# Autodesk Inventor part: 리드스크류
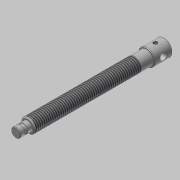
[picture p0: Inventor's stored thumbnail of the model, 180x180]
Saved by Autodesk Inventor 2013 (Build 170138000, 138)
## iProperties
Created: 2019-04
Part Number: 리드스크류
Material: 강철, 연강
Document SubType Name: Modeling
Designer: mduedu
Density: 1 g/cm^3
Author: mduedu
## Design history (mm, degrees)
sketch "스케치1"
  geometry: C1 r 6 at (0, 0); 1 further point
  constraints: 1 centre point, 1 coincident
  dimensions: "d0" = 12 diameter of C1
extrude "돌출1" new body sketch "스케치1" distance "d1" = 100; taper "d2" = 0 deg
sketch "스케치2"
  geometry: C1 r 4 at (0, 0); 1 further point
  constraints: 1 centre point, 1 coincident
  dimensions: "d3" = 8 diameter of C1
extrude "돌출2" join sketch "스케치2" distance "d4" = 10; taper "d5" = 0 deg
sketch "스케치3"
  geometry: C1 r 7 at (0, 0); 1 further point
  constraints: 1 centre point, 1 coincident
  dimensions: "d9" = 14 diameter of C1
extrude "돌출3" join sketch "스케치3" distance "d10" = 15; taper "d11" = 0 deg
feature "스레드1" dims "d12" = 90, "d13" = 0
chamfer "모따기2" distance "d14" = 1; stored, may be unused: second distance "d15" = 2, angle "d16" = 45 deg
chamfer "모따기3" distance "d17" = 0.5; stored, may be unused: second distance "d18" = 2, angle "d19" = 45 deg
chamfer "모따기4" distance "d20" = 0.5; stored, may be unused: second distance "d21" = 2, angle "d22" = 45 deg
sketch "스케치4"
  geometry: L1 (-100, -5)-(-100, 5) reference; L2 (-109.5, 4)-(-109.5, -4) reference; L3 (-109.5, 0)-(-100, 0); C1 r 1.25 at (-105, 4); 1 further point
  constraints: 2 end point, 2 midpoint, 1 centre point
  dimensions: "d23" = 2.5 diameter of C1; "d24" = 5 distance from line of C1.centre L1; "d25" = 4 distance from line of C1.centre L3
revolve "회전1" sketch "스케치4" stored, may be unused: angle "d26" = 90 deg
sketch "스케치5"
  geometry: L1 (0, -6.5)-(0, 6.5) reference; C1 r 3 at (7.5, 0); 2 further points
  constraints: 1 centre point, 1 horizontal alignment, 1 midpoint
  dimensions: "d27" = 6 diameter of C1; "d28" = 7.5 distance from line of C1.centre L1
extrude "돌출4" cut sketch "스케치5" stored distance "d29" = 15; taper "d30" = 0 deg
node "작업 평면1"
sketch "스케치6"
  geometry: L1 (0, 6.5)-(0, -6.5) reference; 2 further points
  constraints: 1 horizontal alignment
  dimensions: "d31" = 7.5 distance from line of point (-7.5, 0) L1
hole "구멍1" sketch "스케치6" at (-7.5, 0) diameter "d32" = 3.242; stored, may be unused: countersink angle "d36" = 90 deg, drill point angle "d38" = 118 deg; dims "d33" = 6, "d34" = 4, "d35" = 2, "d37" = 8
node "솔리드1"
